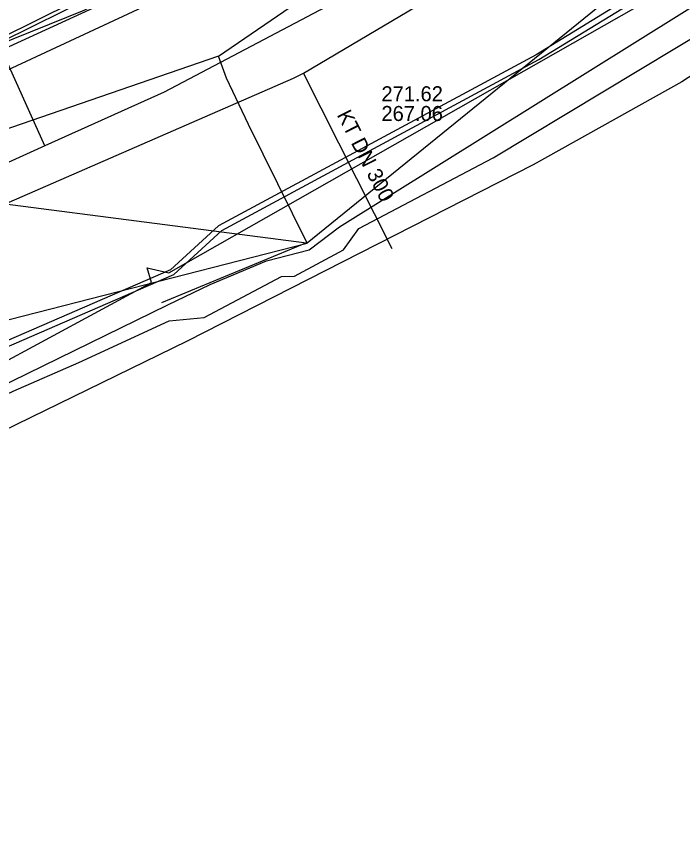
# Model space of a CAD drawing. Extents: x -600309 to -598967, y -1161267 to -1160292.
# Drawn here: x -599592.36 to -599556.9, y -1160601.17 to -1160557.43 of the extents above; entities that cross this region are included whole.
import ezdxf

# ---------------------------------------------------------------- set-up
doc = ezdxf.new("R2010")
doc.units = 0
for name, color, linetype in [('Vrstva 12', 7, 'Continuous'), ('Vrstva 13', 7, 'Continuous'), ('Vrstva 19', 7, 'Continuous'), ('Vrstva 42', 7, 'Continuous'), ('Vrstva 44', 7, 'Continuous'), ('Vrstva 54', 7, 'Continuous'), ('Vrstva 55', 7, 'Continuous'), ('Vrstva 9', 7, 'Continuous')]:
    doc.layers.add(name, color=color, linetype=linetype)

msp = doc.modelspace()

# ---------------------------------------------------------------- linework, layer by layer
at = {"layer": 'Vrstva 12'}
for points in [[(-599595.97, -1160560.5), (-599582.23, -1160554.18), (-599578.84, -1160552.6), (-599578.62, -1160552.47), (-599565.34, -1160544.46), (-599550.78, -1160534.74), (-599547.45, -1160532.52), (-599534.75, -1160524.04), (-599533.94, -1160523.5), (-599533.83, -1160523.46), (-599533.59, -1160523.41), (-599533.52, -1160523.42), (-599533.39, -1160523.47), (-599533.03, -1160523.75)], [(-599606.65, -1160564.32), (-599588.75, -1160557.1), (-599578.92, -1160552.13), (-599565.52, -1160544.47), (-599550.82, -1160534.69), (-599547.73, -1160532.53)], [(-599582.05, -1160571.71), (-599579.05, -1160570.45), (-599576.77, -1160569.87), (-599575.16, -1160568.63), (-599543.57, -1160548.9), (-599538.13, -1160546.56), (-599536.13, -1160545.6), (-599534.74, -1160544.44), (-599528.51, -1160540.33)], [(-599589.04, -1160575.86), (-599584.22, -1160573.64), (-599582.36, -1160573.46), (-599578.24, -1160571.29), (-599577.56, -1160571.27), (-599574.95, -1160569.87), (-599574.13, -1160568.73), (-599566.99, -1160564.97), (-599555.31, -1160557.93)], [(-599601.33, -1160581.6), (-599595.08, -1160578.06), (-599584.29, -1160572.8), (-599582.05, -1160571.71)], [(-599602.82, -1160588.13), (-599602.6, -1160585.47), (-599603.84, -1160582.73), (-599592.53, -1160577.4), (-599589.04, -1160575.86)]]:
    msp.add_lwpolyline(points, dxfattribs=at)
at = {"layer": 'Vrstva 13'}
for points in [[(-599507.507, -1160514.529), (-599507.53, -1160514.54), (-599518.26, -1160520.52), (-599523.38, -1160523.57), (-599528.43, -1160526.85), (-599539.015, -1160533.855), (-599543.33, -1160536.71), (-599558.58, -1160546.59), (-599568.71, -1160552.83), (-599574.9, -1160556.39), (-599584.5, -1160561.46), (-599590.839, -1160564.32), (-599595.36, -1160566.36), (-599600.89, -1160568.66), (-599614.588, -1160574.458)], [(-599590.839, -1160564.32), (-599593.227, -1160559.04), (-599595.522, -1160552.735)]]:
    msp.add_lwpolyline(points, dxfattribs=at)
at = {"layer": 'Vrstva 19'}
msp.add_lwpolyline([(-599583.34, -1160555.86), (-599597.77, -1160562.58), (-599598.09, -1160562.73), (-599599.19, -1160563.24)], dxfattribs=at)
at = {"layer": 'Vrstva 42'}
for points in [[(-599666.89, -1160598.93), (-599646, -1160593.56), (-599627.024, -1160588.712), (-599626.05, -1160588.597), (-599620.906, -1160587.088), (-599619.178, -1160585.949), (-599608.041, -1160583.082), (-599604.829, -1160581.685), (-599604.224, -1160580.426), (-599601.401, -1160578.744), (-599583.987, -1160571.178), (-599581.422, -1160568.833), (-599564.545, -1160559.73), (-599553.619, -1160553.027), (-599534.447, -1160540.365), (-599529.131, -1160536.863), (-599521.749, -1160532), (-599519.689, -1160531.507), (-599518.527, -1160531.293), (-599517.145, -1160530.496), (-599513.153, -1160528.355), (-599510.709, -1160528.041), (-599507.8, -1160528.391), (-599506.615, -1160528.534)], [(-599666.89, -1160598.93), (-599646, -1160593.56), (-599627.024, -1160588.712), (-599626.05, -1160588.597), (-599620.906, -1160587.088), (-599619.178, -1160585.949), (-599608.041, -1160583.082), (-599604.829, -1160581.685), (-599604.224, -1160580.426), (-599601.401, -1160578.744), (-599583.987, -1160571.178), (-599581.422, -1160568.833), (-599564.545, -1160559.73), (-599553.619, -1160553.027), (-599534.447, -1160540.365), (-599529.131, -1160536.863), (-599521.749, -1160532), (-599519.689, -1160531.507), (-599518.527, -1160531.293), (-599517.145, -1160530.496), (-599513.153, -1160528.355), (-599510.709, -1160528.041), (-599507.8, -1160528.391), (-599506.615, -1160528.534)], [(-599517.582, -1160529.978), (-599517.291, -1160530.234), (-599518.633, -1160531.007), (-599519.751, -1160531.213), (-599521.871, -1160531.72), (-599534.613, -1160540.115), (-599553.781, -1160552.773), (-599564.695, -1160559.47), (-599581.598, -1160568.587), (-599584.153, -1160570.922), (-599601.539, -1160578.476), (-599604.456, -1160580.214), (-599605.051, -1160581.455), (-599608.139, -1160582.798), (-599619.302, -1160585.671), (-599621.034, -1160586.812), (-599626.132, -1160588.309), (-599627.098, -1160588.421), (-599646.074, -1160593.269), (-599666.956, -1160598.637)], [(-599517.582, -1160529.978), (-599517.291, -1160530.234), (-599518.633, -1160531.007), (-599519.751, -1160531.213), (-599521.871, -1160531.72), (-599534.613, -1160540.115), (-599553.781, -1160552.773), (-599564.695, -1160559.47), (-599581.598, -1160568.587), (-599584.153, -1160570.922), (-599601.539, -1160578.476), (-599604.456, -1160580.214), (-599605.051, -1160581.455), (-599608.139, -1160582.798), (-599619.302, -1160585.671), (-599621.034, -1160586.812), (-599626.132, -1160588.309), (-599627.098, -1160588.421), (-599646.074, -1160593.269), (-599666.956, -1160598.637)], [(-599583.486, -1160553.761), (-599593.232, -1160558.609), (-599603.928, -1160563.257), (-599606.356, -1160564.312), (-599606.416, -1160564.319), (-599608.322, -1160564.525), (-599608.354, -1160564.528), (-599610.655, -1160563.512), (-599611.051, -1160563.337), (-599611.563, -1160562.793), (-599612.739, -1160561.543), (-599613.09, -1160561.169), (-599613.34, -1160560.904), (-599613.239, -1160560.767), (-599613.096, -1160560.576), (-599612.395, -1160559.631)], [(-599583.394, -1160553.939), (-599593.148, -1160558.791), (-599603.303, -1160563.204), (-599606.304, -1160564.508), (-599607.196, -1160564.604), (-599607.756, -1160564.664), (-599608.386, -1160564.732), (-599610.768, -1160563.68), (-599611.169, -1160563.503), (-599612.268, -1160562.335), (-599612.562, -1160562.023), (-599612.913, -1160561.65), (-599613.265, -1160561.276), (-599613.303, -1160561.235), (-599613.66, -1160560.856), (-599613.501, -1160560.659), (-599613.495, -1160560.651), (-599613.348, -1160560.47), (-599613.202, -1160560.289), (-599612.724, -1160559.697)], [(-599601.607, -1160566.301), (-599576.926, -1160569.49)], [(-599576.926, -1160569.49), (-599584.64, -1160572.678)]]:
    msp.add_lwpolyline(points, dxfattribs=at)
at = {"layer": 'Vrstva 44'}
msp.add_lwpolyline([(-599510.704, -1160534.267), (-599513.257, -1160533.559), (-599514.327, -1160533.609), (-599515.777, -1160534.409), (-599516.977, -1160535.299), (-599528.107, -1160542.029), (-599543.307, -1160552.019), (-599556.937, -1160560.919), (-599564.847, -1160565.339), (-599583.267, -1160574.729), (-599593.117, -1160579.539), (-599605.707, -1160585.219), (-599609.457, -1160586.109), (-599616.817, -1160588.829), (-599618.477, -1160589.829), (-599619.532, -1160590.524), (-599619.647, -1160590.599), (-599619.677, -1160591.139), (-599619.477, -1160591.739)], dxfattribs=at)
at = {"layer": 'Vrstva 54'}
for points in [[(-599581.61, -1160559.54), (-599562.75, -1160546.64)], [(-599558.21, -1160554.34), (-599576.89, -1160569.51)], [(-599581.61, -1160559.54), (-599601.54, -1160566.42)], [(-599581.17, -1160560.72), (-599581.61, -1160559.54)], [(-599580, -1160563.18), (-599581.17, -1160560.72)], [(-599576.89, -1160569.51), (-599580, -1160563.18)], [(-599598.51, -1160575.04), (-599576.89, -1160569.51)]]:
    msp.add_lwpolyline(points, dxfattribs=at)
at = {"layer": 'Vrstva 55'}
msp.add_lwpolyline([(-599683.03, -1160601.17), (-599683.18, -1160599.83), (-599651.44, -1160592.06), (-599650.772, -1160593.118), (-599650.29, -1160591.81), (-599622.163, -1160585.674), (-599620.809, -1160585.449), (-599610.1, -1160582.19), (-599608.78, -1160582.26), (-599596.47, -1160577.71), (-599585.17, -1160571.6), (-599585.396, -1160570.825), (-599584.25, -1160571.09), (-599549.91, -1160551.54), (-599516.862, -1160529.283), (-599512.86, -1160534.75), (-599497.37, -1160526.78), (-599489.12, -1160522.63), (-599486.71, -1160527.61)], dxfattribs=at)
at = {"layer": 'Vrstva 9'}
msp.add_line((-599572.349, -1160569.803), (-599577.085, -1160560.455), dxfattribs=at)
for points in [[(-599577.085, -1160560.455), (-599563.825, -1160552.588), (-599556.162, -1160548.042), (-599556.093, -1160548.002), (-599543.33, -1160540.43)], [(-599611.225, -1160575.388), (-599577.616, -1160560.723), (-599577.085, -1160560.455)]]:
    msp.add_lwpolyline(points, dxfattribs=at)

# ---------------------------------------------------------------- texts
at = {"layer": 'Vrstva 12'}
for s, p in [('271.62', (-599572.929, -1160561.95)), ('267.06', (-599572.929, -1160563))]:
    msp.add_text(s, height=0.8, dxfattribs=at).set_placement(p)
msp.add_text('KT DN 300', height=0.8, rotation=296.8663, dxfattribs=at).set_placement((-599575.318, -1160562.666))

doc.saveas('drawing.dxf')
